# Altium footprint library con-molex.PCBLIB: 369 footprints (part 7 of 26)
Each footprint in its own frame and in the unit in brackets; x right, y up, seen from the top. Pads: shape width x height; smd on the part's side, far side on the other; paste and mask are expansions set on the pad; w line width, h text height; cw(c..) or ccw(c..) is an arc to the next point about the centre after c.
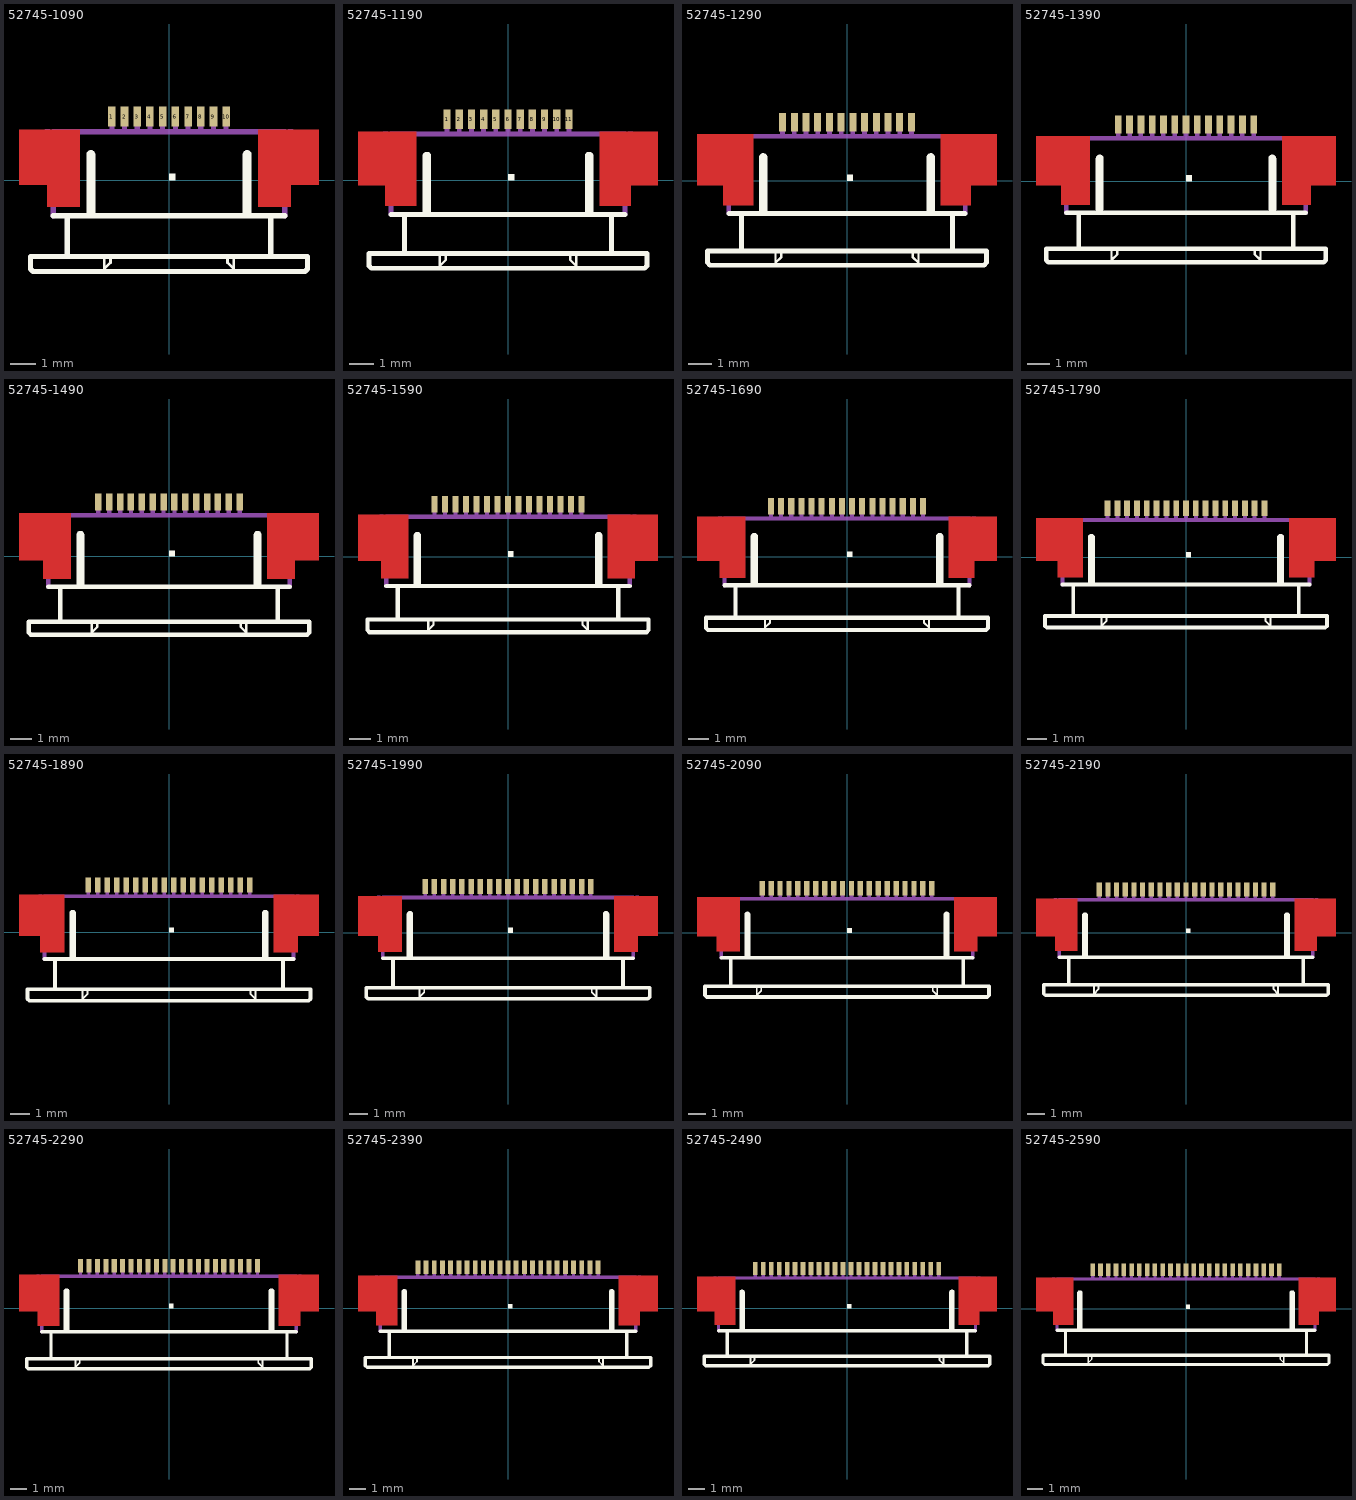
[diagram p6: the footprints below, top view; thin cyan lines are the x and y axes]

## 52745-1090 [mil]
pads (10):
  rect 11.81x31.5 smd: 1(-88.58,98.43) 2(-68.9,98.43) 3(-49.21,98.43) 4(-29.53,98.43) 5(-9.84,98.43) 6(9.84,98.43) 7(29.53,98.43) 8(49.21,98.43) 9(68.9,98.43) 10(88.58,98.43)
Top Layer:
  rectangle: -232.28,-7.87 -137.8,78.74
  rectangle: -188.98,-41.34 -137.8,-7.87
  rectangle: 137.8,-41.34 188.98,-7.87
  rectangle: 137.8,-7.87 232.28,78.74
Top Overlay:
  region: 0,0 10,0 10,10 0,10
  lines w4: -100.39,-122.05 -100.39,-137.8 -90.55,-127.95 -90.55,-122.05 ; 90.55,-122.05 90.55,-127.95 100.39,-137.8 100.39,-122.05
  lines w8: -179.13,-55.12 179.13,-55.12 ; -157.48,-114.17 -157.48,-59.06 ; -124.02,-49.21 -124.02,39.37 cw(c-121.06,39.37) -118.11,39.37 -118.11,-49.21 ; 118.11,-49.21 118.11,39.37 cw(c121.06,39.37) 124.02,39.37 124.02,-49.21 ; 157.48,-114.17 157.48,-59.06 ; -214.57,-137.8 -214.57,-118.11 214.57,-118.11 214.57,-137.8 210.63,-141.73 -210.63,-141.73 -214.57,-137.8
Top Paste:
  region: 224.41,72.83 145.67,72.83 145.67,-1.97 224.41,-1.97
  rectangle: -224.41,-1.97 -145.67,72.83
Top Solder:
  region: 232.28,78.74 187.01,78.74 187.01,-7.87 232.28,-7.87
  region: 188.98,78.74 137.8,78.74 137.8,-41.34 188.98,-41.34
  rectangle: -232.28,-7.87 -187.01,78.74
  rectangle: -188.98,-41.34 -137.8,78.74
Mechanical 16:
  rectangle: -92.52,78.74 -84.65,106.3
  rectangle: -72.83,78.74 -64.96,106.3
  rectangle: -53.15,78.74 -45.28,106.3
  rectangle: -33.46,78.74 -25.59,106.3
  rectangle: -13.78,78.74 -5.91,106.3
  rectangle: 5.91,78.74 13.78,106.3
  rectangle: 25.59,78.74 33.46,106.3
  rectangle: 45.28,78.74 53.15,106.3
  rectangle: 64.96,78.74 72.83,106.3
  rectangle: 84.65,78.74 92.52,106.3
  lines w4: -185.04,74.8 -185.04,27.56 -214.57,27.56 -214.57,35.43 -192.91,35.43 -190.94,37.4 -190.94,57.09 -214.57,57.09 -214.57,64.96 -190.94,64.96 -190.94,76.77 -185.04,76.77 ; 185.04,74.8 185.04,27.56 214.57,27.56 214.57,35.43 192.91,35.43 190.94,37.4 190.94,57.09 214.57,57.09 214.57,64.96 190.94,64.96 190.94,76.77 185.04,76.77
  lines w8: -179.13,-55.12 -179.13,74.8 179.13,74.8 179.13,-55.12

## 52745-1190 [mil]
pads (11):
  rect 11.81x31.5 smd: 1(-98.43,98.43) 2(-78.74,98.43) 3(-59.06,98.43) 4(-39.37,98.43) 5(-19.69,98.43) 6(0,98.43) 7(19.69,98.43) 8(39.37,98.43) 9(59.06,98.43) 10(78.74,98.43) 11(98.43,98.43)
Top Layer:
  rectangle: -242.13,-7.87 -147.64,78.74
  rectangle: -198.82,-41.34 -147.64,-7.87
  rectangle: 147.64,-41.34 198.82,-7.87
  rectangle: 147.64,-7.87 242.13,78.74
Top Overlay:
  region: 0,0 10,0 10,10 0,10
  lines w4: -110.24,-122.05 -110.24,-137.8 -100.39,-127.95 -100.39,-122.05 ; 100.39,-122.05 100.39,-127.95 110.24,-137.8 110.24,-122.05
  lines w8: -188.98,-55.12 188.98,-55.12 ; -167.32,-114.17 -167.32,-59.06 ; -133.86,-49.21 -133.86,39.37 cw(c-130.91,39.37) -127.95,39.37 -127.95,-49.21 ; 127.95,-49.21 127.95,39.37 cw(c130.91,39.37) 133.86,39.37 133.86,-49.21 ; 167.32,-114.17 167.32,-59.06 ; -224.41,-137.8 -224.41,-118.11 224.41,-118.11 224.41,-137.8 220.47,-141.73 -220.47,-141.73 -224.41,-137.8
Top Paste:
  region: 234.25,72.83 155.51,72.83 155.51,-1.97 234.25,-1.97
  rectangle: -234.25,-1.97 -155.51,72.83
Top Solder:
  region: 242.13,78.74 196.85,78.74 196.85,-7.87 242.13,-7.87
  region: 198.82,78.74 147.64,78.74 147.64,-41.34 198.82,-41.34
  rectangle: -242.13,-7.87 -196.85,78.74
  rectangle: -198.82,-41.34 -147.64,78.74
Mechanical 16:
  rectangle: -102.36,78.74 -94.49,106.3
  rectangle: -82.68,78.74 -74.8,106.3
  rectangle: -62.99,78.74 -55.12,106.3
  rectangle: -43.31,78.74 -35.43,106.3
  rectangle: -23.62,78.74 -15.75,106.3
  rectangle: -3.94,78.74 3.94,106.3
  rectangle: 15.75,78.74 23.62,106.3
  rectangle: 35.43,78.74 43.31,106.3
  rectangle: 55.12,78.74 62.99,106.3
  rectangle: 74.8,78.74 82.68,106.3
  rectangle: 94.49,78.74 102.36,106.3
  lines w4: -194.88,74.8 -194.88,27.56 -224.41,27.56 -224.41,35.43 -202.76,35.43 -200.79,37.4 -200.79,57.09 -224.41,57.09 -224.41,64.96 -200.79,64.96 -200.79,76.77 -194.88,76.77 ; 194.88,74.8 194.88,27.56 224.41,27.56 224.41,35.43 202.76,35.43 200.79,37.4 200.79,57.09 224.41,57.09 224.41,64.96 200.79,64.96 200.79,76.77 194.88,76.77
  lines w8: -188.98,-55.12 -188.98,74.8 188.98,74.8 188.98,-55.12

## 52745-1290 [mil]
pads (12):
  rect 11.81x31.5 smd: 1(-108.27,98.43) 2(-88.58,98.43) 3(-68.9,98.43) 4(-49.21,98.43) 5(-29.53,98.43) 6(-9.84,98.43) 7(9.84,98.43) 8(29.53,98.43) 9(49.21,98.43) 10(68.9,98.43) 11(88.58,98.43) 12(108.27,98.43)
Top Layer:
  rectangle: -251.97,-7.87 -157.48,78.74
  rectangle: -208.66,-41.34 -157.48,-7.87
  rectangle: 157.48,-7.87 251.97,78.74
  rectangle: 157.48,-41.34 208.66,-7.87
Top Overlay:
  region: 0,0 10,0 10,10 0,10
  lines w4: -120.08,-122.05 -120.08,-137.8 -110.24,-127.95 -110.24,-122.05 ; 110.24,-122.05 110.24,-127.95 120.08,-137.8 120.08,-122.05
  lines w8: -198.82,-55.12 198.82,-55.12 ; -177.17,-114.17 -177.17,-59.06 ; -143.7,-49.21 -143.7,39.37 cw(c-140.75,39.37) -137.8,39.37 -137.8,-49.21 ; 137.8,-49.21 137.8,39.37 cw(c140.75,39.37) 143.7,39.37 143.7,-49.21 ; 177.17,-114.17 177.17,-59.06 ; -234.25,-137.8 -234.25,-118.11 234.25,-118.11 234.25,-137.8 230.32,-141.73 -230.32,-141.73 -234.25,-137.8
Top Paste:
  region: 244.09,72.83 165.35,72.83 165.35,-1.97 244.09,-1.97
  rectangle: -244.09,-1.97 -165.35,72.83
Top Solder:
  region: 251.97,78.74 206.69,78.74 206.69,-7.87 251.97,-7.87
  region: 208.66,78.74 157.48,78.74 157.48,-41.34 208.66,-41.34
  rectangle: -251.97,-7.87 -206.69,78.74
  rectangle: -208.66,-41.34 -157.48,78.74
Mechanical 16:
  rectangle: -112.2,78.74 -104.33,106.3
  rectangle: -92.52,78.74 -84.65,106.3
  rectangle: -72.83,78.74 -64.96,106.3
  rectangle: -53.15,78.74 -45.28,106.3
  rectangle: -33.46,78.74 -25.59,106.3
  rectangle: -13.78,78.74 -5.91,106.3
  rectangle: 5.91,78.74 13.78,106.3
  rectangle: 25.59,78.74 33.46,106.3
  rectangle: 45.28,78.74 53.15,106.3
  rectangle: 64.96,78.74 72.83,106.3
  rectangle: 84.65,78.74 92.52,106.3
  rectangle: 104.33,78.74 112.2,106.3
  lines w4: -204.72,74.8 -204.72,27.56 -234.25,27.56 -234.25,35.43 -212.6,35.43 -210.63,37.4 -210.63,57.09 -234.25,57.09 -234.25,64.96 -210.63,64.96 -210.63,76.77 -204.72,76.77 ; 204.72,74.8 204.72,27.56 234.25,27.56 234.25,35.43 212.6,35.43 210.63,37.4 210.63,57.09 234.25,57.09 234.25,64.96 210.63,64.96 210.63,76.77 204.72,76.77
  lines w8: -198.82,-55.12 -198.82,74.8 198.82,74.8 198.82,-55.12

## 52745-1390 [mil]
pads (13):
  rect 11.81x31.5 smd: 1(-118.11,98.43) 2(-98.43,98.43) 3(-78.74,98.43) 4(-59.06,98.43) 5(-39.37,98.43) 6(-19.69,98.43) 7(0,98.43) 8(19.69,98.43) 9(39.37,98.43) 10(59.06,98.43) 11(78.74,98.43) 12(98.43,98.43) 13(118.11,98.43)
Top Layer:
  rectangle: -261.81,-7.87 -167.32,78.74
  rectangle: -218.5,-41.34 -167.32,-7.87
  rectangle: 167.32,-7.87 261.81,78.74
  rectangle: 167.32,-41.34 218.5,-7.87
Top Overlay:
  region: 0,0 10,0 10,10 0,10
  lines w4: -129.92,-122.05 -129.92,-137.8 -120.08,-127.95 -120.08,-122.05 ; 120.08,-122.05 120.08,-127.95 129.92,-137.8 129.92,-122.05
  lines w8: -208.66,-55.12 208.66,-55.12 ; -187.01,-114.17 -187.01,-59.06 ; -153.54,-49.21 -153.54,39.37 cw(c-150.59,39.37) -147.64,39.37 -147.64,-49.21 ; 147.64,-49.21 147.64,39.37 cw(c150.59,39.37) 153.54,39.37 153.54,-49.21 ; 187.01,-114.17 187.01,-59.06 ; -244.09,-137.8 -244.09,-118.11 244.09,-118.11 244.09,-137.8 240.16,-141.73 -240.16,-141.73 -244.09,-137.8
Top Paste:
  region: 253.94,72.83 175.2,72.83 175.2,-1.97 253.94,-1.97
  rectangle: -253.94,-1.97 -175.2,72.83
Top Solder:
  region: 261.81,78.74 216.54,78.74 216.54,-7.87 261.81,-7.87
  region: 218.5,78.74 167.32,78.74 167.32,-41.34 218.5,-41.34
  rectangle: -261.81,-7.87 -216.54,78.74
  rectangle: -218.5,-41.34 -167.32,78.74
Mechanical 16:
  rectangle: -122.05,78.74 -114.17,106.3
  rectangle: -102.36,78.74 -94.49,106.3
  rectangle: -82.68,78.74 -74.8,106.3
  rectangle: -62.99,78.74 -55.12,106.3
  rectangle: -43.31,78.74 -35.43,106.3
  rectangle: -23.62,78.74 -15.75,106.3
  rectangle: -3.94,78.74 3.94,106.3
  rectangle: 15.75,78.74 23.62,106.3
  rectangle: 35.43,78.74 43.31,106.3
  rectangle: 55.12,78.74 62.99,106.3
  rectangle: 74.8,78.74 82.68,106.3
  rectangle: 94.49,78.74 102.36,106.3
  rectangle: 114.17,78.74 122.05,106.3
  lines w4: -214.57,74.8 -214.57,27.56 -244.09,27.56 -244.09,35.43 -222.44,35.43 -220.47,37.4 -220.47,57.09 -244.09,57.09 -244.09,64.96 -220.47,64.96 -220.47,76.77 -214.57,76.77 ; 214.57,74.8 214.57,27.56 244.09,27.56 244.09,35.43 222.44,35.43 220.47,37.4 220.47,57.09 244.09,57.09 244.09,64.96 220.47,64.96 220.47,76.77 214.57,76.77
  lines w8: -208.66,-55.12 -208.66,74.8 208.66,74.8 208.66,-55.12

## 52745-1490 [mil]
pads (14):
  rect 11.81x31.5 smd: 1(-127.95,98.43) 2(-108.27,98.43) 3(-88.58,98.43) 4(-68.9,98.43) 5(-49.21,98.43) 6(-29.53,98.43) 7(-9.84,98.43) 8(9.84,98.43) 9(29.53,98.43) 10(49.21,98.43) 11(68.9,98.43) 12(88.58,98.43) 13(108.27,98.43) 14(127.95,98.43)
Top Layer:
  rectangle: -271.65,-7.87 -177.17,78.74
  rectangle: -228.35,-41.34 -177.17,-7.87
  rectangle: 177.17,-7.87 271.65,78.74
  rectangle: 177.17,-41.34 228.35,-7.87
Top Overlay:
  region: 0,0 10,0 10,10 0,10
  lines w4: -139.76,-122.05 -139.76,-137.8 -129.92,-127.95 -129.92,-122.05 ; 129.92,-122.05 129.92,-127.95 139.76,-137.8 139.76,-122.05
  lines w8: -218.5,-55.12 218.5,-55.12 ; -196.85,-114.17 -196.85,-59.06 ; -163.39,-49.21 -163.39,39.37 cw(c-160.44,39.37) -157.48,39.37 -157.48,-49.21 ; 157.48,-49.21 157.48,39.37 cw(c160.44,39.37) 163.39,39.37 163.39,-49.21 ; 196.85,-114.17 196.85,-59.06 ; -253.94,-137.8 -253.94,-118.11 253.94,-118.11 253.94,-137.8 250,-141.73 -250,-141.73 -253.94,-137.8
Top Paste:
  region: 263.78,72.83 185.04,72.83 185.04,-1.97 263.78,-1.97
  rectangle: -263.78,-1.97 -185.04,72.83
Top Solder:
  region: 271.65,78.74 226.38,78.74 226.38,-7.87 271.65,-7.87
  region: 228.35,78.74 177.17,78.74 177.17,-41.34 228.35,-41.34
  rectangle: -271.65,-7.87 -226.38,78.74
  rectangle: -228.35,-41.34 -177.17,78.74
Mechanical 16:
  rectangle: -131.89,78.74 -124.02,106.3
  rectangle: -112.2,78.74 -104.33,106.3
  rectangle: -92.52,78.74 -84.65,106.3
  rectangle: -72.83,78.74 -64.96,106.3
  rectangle: -53.15,78.74 -45.28,106.3
  rectangle: -33.46,78.74 -25.59,106.3
  rectangle: -13.78,78.74 -5.91,106.3
  rectangle: 5.91,78.74 13.78,106.3
  rectangle: 25.59,78.74 33.46,106.3
  rectangle: 45.28,78.74 53.15,106.3
  rectangle: 64.96,78.74 72.83,106.3
  rectangle: 84.65,78.74 92.52,106.3
  rectangle: 104.33,78.74 112.2,106.3
  rectangle: 124.02,78.74 131.89,106.3
  lines w4: -224.41,74.8 -224.41,27.56 -253.94,27.56 -253.94,35.43 -232.28,35.43 -230.32,37.4 -230.32,57.09 -253.94,57.09 -253.94,64.96 -230.32,64.96 -230.32,76.77 -224.41,76.77 ; 224.41,74.8 224.41,27.56 253.94,27.56 253.94,35.43 232.28,35.43 230.32,37.4 230.32,57.09 253.94,57.09 253.94,64.96 230.32,64.96 230.32,76.77 224.41,76.77
  lines w8: -218.5,-55.12 -218.5,74.8 218.5,74.8 218.5,-55.12

## 52745-1590 [mil]
pads (15):
  rect 11.81x31.5 smd: 1(-137.8,98.43) 2(-118.11,98.43) 3(-98.43,98.43) 4(-78.74,98.43) 5(-59.06,98.43) 6(-39.37,98.43) 7(-19.69,98.43) 8(0,98.43) 9(19.69,98.43) 10(39.37,98.43) 11(59.06,98.43) 12(78.74,98.43) 13(98.43,98.43) 14(118.11,98.43) 15(137.8,98.43)
Top Layer:
  rectangle: -281.5,-7.87 -187.01,78.74
  rectangle: -238.19,-41.34 -187.01,-7.87
  rectangle: 187.01,-7.87 281.5,78.74
  rectangle: 187.01,-41.34 238.19,-7.87
Top Overlay:
  region: 0,0 10,0 10,10 0,10
  lines w4: -149.61,-122.05 -149.61,-137.8 -139.76,-127.95 -139.76,-122.05 ; 139.76,-122.05 139.76,-127.95 149.61,-137.8 149.61,-122.05
  lines w8: -228.35,-55.12 228.35,-55.12 ; -206.69,-114.17 -206.69,-59.06 ; -173.23,-49.21 -173.23,39.37 cw(c-170.28,39.37) -167.32,39.37 -167.32,-49.21 ; 167.32,-49.21 167.32,39.37 cw(c170.28,39.37) 173.23,39.37 173.23,-49.21 ; 206.69,-114.17 206.69,-59.06 ; -263.78,-137.8 -263.78,-118.11 263.78,-118.11 263.78,-137.8 259.84,-141.73 -259.84,-141.73 -263.78,-137.8
Top Paste:
  region: 273.62,72.83 194.88,72.83 194.88,-1.97 273.62,-1.97
  rectangle: -273.62,-1.97 -194.88,72.83
Top Solder:
  region: 281.5,78.74 236.22,78.74 236.22,-7.87 281.5,-7.87
  region: 238.19,78.74 187.01,78.74 187.01,-41.34 238.19,-41.34
  rectangle: -281.5,-7.87 -236.22,78.74
  rectangle: -238.19,-41.34 -187.01,78.74
Mechanical 16:
  rectangle: -141.73,78.74 -133.86,106.3
  rectangle: -122.05,78.74 -114.17,106.3
  rectangle: -102.36,78.74 -94.49,106.3
  rectangle: -82.68,78.74 -74.8,106.3
  rectangle: -62.99,78.74 -55.12,106.3
  rectangle: -43.31,78.74 -35.43,106.3
  rectangle: -23.62,78.74 -15.75,106.3
  rectangle: -3.94,78.74 3.94,106.3
  rectangle: 15.75,78.74 23.62,106.3
  rectangle: 35.43,78.74 43.31,106.3
  rectangle: 55.12,78.74 62.99,106.3
  rectangle: 74.8,78.74 82.68,106.3
  rectangle: 94.49,78.74 102.36,106.3
  rectangle: 114.17,78.74 122.05,106.3
  rectangle: 133.86,78.74 141.73,106.3
  lines w4: -234.25,74.8 -234.25,27.56 -263.78,27.56 -263.78,35.43 -242.13,35.43 -240.16,37.4 -240.16,57.09 -263.78,57.09 -263.78,64.96 -240.16,64.96 -240.16,76.77 -234.25,76.77 ; 234.25,74.8 234.25,27.56 263.78,27.56 263.78,35.43 242.13,35.43 240.16,37.4 240.16,57.09 263.78,57.09 263.78,64.96 240.16,64.96 240.16,76.77 234.25,76.77
  lines w8: -228.35,-55.12 -228.35,74.8 228.35,74.8 228.35,-55.12

## 52745-1690 [mil]
pads (16):
  rect 11.81x31.5 smd: 1(-147.64,98.43) 2(-127.95,98.43) 3(-108.27,98.43) 4(-88.58,98.43) 5(-68.9,98.43) 6(-49.21,98.43) 7(-29.53,98.43) 8(-9.84,98.43) 9(9.84,98.43) 10(29.53,98.43) 11(49.21,98.43) 12(68.9,98.43) 13(88.58,98.43) 14(108.27,98.43) 15(127.95,98.43) 16(147.64,98.43)
Top Layer:
  rectangle: -291.34,-7.87 -196.85,78.74
  rectangle: -248.03,-41.34 -196.85,-7.87
  rectangle: 196.85,-7.87 291.34,78.74
  rectangle: 196.85,-41.34 248.03,-7.87
Top Overlay:
  region: 0,0 10,0 10,10 0,10
  lines w4: -159.45,-122.05 -159.45,-137.8 -149.61,-127.95 -149.61,-122.05 ; 149.61,-122.05 149.61,-127.95 159.45,-137.8 159.45,-122.05
  lines w8: -238.19,-55.12 238.19,-55.12 ; -216.54,-114.17 -216.54,-59.06 ; -183.07,-49.21 -183.07,39.37 cw(c-180.12,39.37) -177.17,39.37 -177.17,-49.21 ; 177.17,-49.21 177.17,39.37 cw(c180.12,39.37) 183.07,39.37 183.07,-49.21 ; 216.54,-114.17 216.54,-59.06 ; -273.62,-137.8 -273.62,-118.11 273.62,-118.11 273.62,-137.8 269.69,-141.73 -269.69,-141.73 -273.62,-137.8
Top Paste:
  region: 283.46,72.83 204.72,72.83 204.72,-1.97 283.46,-1.97
  rectangle: -283.46,-1.97 -204.72,72.83
Top Solder:
  region: 291.34,78.74 246.06,78.74 246.06,-7.87 291.34,-7.87
  region: 248.03,78.74 196.85,78.74 196.85,-41.34 248.03,-41.34
  rectangle: -291.34,-7.87 -246.06,78.74
  rectangle: -248.03,-41.34 -196.85,78.74
Mechanical 16:
  rectangle: -151.57,78.74 -143.7,106.3
  rectangle: -131.89,78.74 -124.02,106.3
  rectangle: -112.2,78.74 -104.33,106.3
  rectangle: -92.52,78.74 -84.65,106.3
  rectangle: -72.83,78.74 -64.96,106.3
  rectangle: -53.15,78.74 -45.28,106.3
  rectangle: -33.46,78.74 -25.59,106.3
  rectangle: -13.78,78.74 -5.91,106.3
  rectangle: 5.91,78.74 13.78,106.3
  rectangle: 25.59,78.74 33.46,106.3
  rectangle: 45.28,78.74 53.15,106.3
  rectangle: 64.96,78.74 72.83,106.3
  rectangle: 84.65,78.74 92.52,106.3
  rectangle: 104.33,78.74 112.2,106.3
  rectangle: 124.02,78.74 131.89,106.3
  rectangle: 143.7,78.74 151.57,106.3
  lines w4: -244.09,74.8 -244.09,27.56 -273.62,27.56 -273.62,35.43 -251.97,35.43 -250,37.4 -250,57.09 -273.62,57.09 -273.62,64.96 -250,64.96 -250,76.77 -244.09,76.77 ; 244.09,74.8 244.09,27.56 273.62,27.56 273.62,35.43 251.97,35.43 250,37.4 250,57.09 273.62,57.09 273.62,64.96 250,64.96 250,76.77 244.09,76.77
  lines w8: -238.19,-55.12 -238.19,74.8 238.19,74.8 238.19,-55.12

## 52745-1790 [mil]
pads (17):
  rect 11.81x31.5 smd: 1(-157.48,98.43) 2(-137.8,98.43) 3(-118.11,98.43) 4(-98.43,98.43) 5(-78.74,98.43) 6(-59.06,98.43) 7(-39.37,98.43) 8(-19.69,98.43) 9(0,98.43) 10(19.69,98.43) 11(39.37,98.43) 12(59.06,98.43) 13(78.74,98.43) 14(98.43,98.43) 15(118.11,98.43) 16(137.8,98.43) 17(157.48,98.43)
Top Layer:
  rectangle: -301.18,-7.87 -206.69,78.74
  rectangle: -257.87,-41.34 -206.69,-6.89
  rectangle: 206.69,-41.34 257.87,-6.89
  rectangle: 206.69,-7.87 301.18,78.74
Top Overlay:
  region: 0,0 10,0 10,10 0,10
  lines w4: -169.29,-122.05 -169.29,-137.8 -159.45,-127.95 -159.45,-122.05 ; 159.45,-122.05 159.45,-127.95 169.29,-137.8 169.29,-122.05
  lines w8: -248.03,-55.12 248.03,-55.12 ; -226.38,-114.17 -226.38,-59.06 ; -192.91,-49.21 -192.91,39.37 cw(c-189.96,39.37) -187.01,39.37 -187.01,-49.21 ; 187.01,-49.21 187.01,39.37 cw(c189.96,39.37) 192.91,39.37 192.91,-49.21 ; 226.38,-114.17 226.38,-59.06 ; -283.46,-137.8 -283.46,-118.11 283.46,-118.11 283.46,-137.8 279.53,-141.73 -279.53,-141.73 -283.46,-137.8
Top Paste:
  region: 293.31,72.83 214.57,72.83 214.57,-1.97 293.31,-1.97
  rectangle: -293.31,-1.97 -214.57,72.83
Top Solder:
  region: 301.18,78.74 255.91,78.74 255.91,-7.87 301.18,-7.87
  region: 257.87,78.74 206.69,78.74 206.69,-41.34 257.87,-41.34
  rectangle: -301.18,-7.87 -255.91,78.74
  rectangle: -257.87,-41.34 -206.69,78.74
Mechanical 16:
  rectangle: -161.42,78.74 -153.54,106.3
  rectangle: -141.73,78.74 -133.86,106.3
  rectangle: -122.05,78.74 -114.17,106.3
  rectangle: -102.36,78.74 -94.49,106.3
  rectangle: -82.68,78.74 -74.8,106.3
  rectangle: -62.99,78.74 -55.12,106.3
  rectangle: -43.31,78.74 -35.43,106.3
  rectangle: -23.62,78.74 -15.75,106.3
  rectangle: -3.94,78.74 3.94,106.3
  rectangle: 15.75,78.74 23.62,106.3
  rectangle: 35.43,78.74 43.31,106.3
  rectangle: 55.12,78.74 62.99,106.3
  rectangle: 74.8,78.74 82.68,106.3
  rectangle: 94.49,78.74 102.36,106.3
  rectangle: 114.17,78.74 122.05,106.3
  rectangle: 133.86,78.74 141.73,106.3
  rectangle: 153.54,78.74 161.42,106.3
  lines w4: -253.94,74.8 -253.94,27.56 -283.46,27.56 -283.46,35.43 -261.81,35.43 -259.84,37.4 -259.84,57.09 -283.46,57.09 -283.46,64.96 -259.84,64.96 -259.84,76.77 -253.94,76.77 ; 253.94,74.8 253.94,27.56 283.46,27.56 283.46,35.43 261.81,35.43 259.84,37.4 259.84,57.09 283.46,57.09 283.46,64.96 259.84,64.96 259.84,76.77 253.94,76.77
  lines w8: -248.03,-55.12 -248.03,74.8 248.03,74.8 248.03,-55.12

## 52745-1890 [mil]
pads (18):
  rect 11.81x31.5 smd: 1(-167.32,98.43) 2(-147.64,98.43) 3(-127.95,98.43) 4(-108.27,98.43) 5(-88.58,98.43) 6(-68.9,98.43) 7(-49.21,98.43) 8(-29.53,98.43) 9(-9.84,98.43) 10(9.84,98.43) 11(29.53,98.43) 12(49.21,98.43) 13(68.9,98.43) 14(88.58,98.43) 15(108.27,98.43) 16(127.95,98.43) 17(147.64,98.43) 18(167.32,98.43)
Top Layer:
  rectangle: -311.02,-7.87 -216.54,78.74
  rectangle: -267.72,-41.34 -216.54,-7.87
  rectangle: 216.54,-41.34 267.72,-7.87
  rectangle: 216.54,-7.87 311.02,78.74
Top Overlay:
  region: 0,0 10,0 10,10 0,10
  lines w4: -179.13,-122.05 -179.13,-137.8 -169.29,-127.95 -169.29,-122.05 ; 169.29,-122.05 169.29,-127.95 179.13,-137.8 179.13,-122.05
  lines w8: -257.87,-55.12 257.87,-55.12 ; -236.22,-114.17 -236.22,-59.06 ; -202.76,-49.21 -202.76,39.37 cw(c-199.81,39.37) -196.85,39.37 -196.85,-49.21 ; 196.85,-49.21 196.85,39.37 cw(c199.81,39.37) 202.76,39.37 202.76,-49.21 ; 236.22,-114.17 236.22,-59.06 ; -293.31,-137.8 -293.31,-118.11 293.31,-118.11 293.31,-137.8 289.37,-141.73 -289.37,-141.73 -293.31,-137.8
Top Paste:
  region: 303.15,72.83 224.41,72.83 224.41,-1.97 303.15,-1.97
  rectangle: -303.15,-1.97 -224.41,72.83
Top Solder:
  region: 311.02,78.74 265.75,78.74 265.75,-7.87 311.02,-7.87
  region: 267.72,78.74 216.54,78.74 216.54,-41.34 267.72,-41.34
  rectangle: -311.02,-7.87 -265.75,78.74
  rectangle: -267.72,-41.34 -216.54,78.74
Mechanical 16:
  rectangle: -171.26,78.74 -163.39,106.3
  rectangle: -151.57,78.74 -143.7,106.3
  rectangle: -131.89,78.74 -124.02,106.3
  rectangle: -112.2,78.74 -104.33,106.3
  rectangle: -92.52,78.74 -84.65,106.3
  rectangle: -72.83,78.74 -64.96,106.3
  rectangle: -53.15,78.74 -45.28,106.3
  rectangle: -33.46,78.74 -25.59,106.3
  rectangle: -13.78,78.74 -5.91,106.3
  rectangle: 5.91,78.74 13.78,106.3
  rectangle: 25.59,78.74 33.46,106.3
  rectangle: 45.28,78.74 53.15,106.3
  rectangle: 64.96,78.74 72.83,106.3
  rectangle: 84.65,78.74 92.52,106.3
  rectangle: 104.33,78.74 112.2,106.3
  rectangle: 124.02,78.74 131.89,106.3
  rectangle: 143.7,78.74 151.57,106.3
  rectangle: 163.39,78.74 171.26,106.3
  lines w4: -263.78,74.8 -263.78,27.56 -293.31,27.56 -293.31,35.43 -271.65,35.43 -269.69,37.4 -269.69,57.09 -293.31,57.09 -293.31,64.96 -269.69,64.96 -269.69,76.77 -263.78,76.77 ; 263.78,74.8 263.78,27.56 293.31,27.56 293.31,35.43 271.65,35.43 269.69,37.4 269.69,57.09 293.31,57.09 293.31,64.96 269.69,64.96 269.69,76.77 263.78,76.77
  lines w8: -257.87,-55.12 -257.87,74.8 257.87,74.8 257.87,-55.12

## 52745-1990 [mil]
pads (19):
  rect 11.81x31.5 smd: 1(-177.17,98.43) 2(-157.48,98.43) 3(-137.8,98.43) 4(-118.11,98.43) 5(-98.43,98.43) 6(-78.74,98.43) 7(-59.06,98.43) 8(-39.37,98.43) 9(-19.69,98.43) 10(0,98.43) 11(19.69,98.43) 12(39.37,98.43) 13(59.06,98.43) 14(78.74,98.43) 15(98.43,98.43) 16(118.11,98.43) 17(137.8,98.43) 18(157.48,98.43) 19(177.17,98.43)
Top Layer:
  rectangle: -320.87,-7.87 -226.38,78.74
  rectangle: -277.56,-41.34 -226.38,-7.87
  rectangle: 226.38,-41.34 277.56,-7.87
  rectangle: 226.38,-7.87 320.87,78.74
Top Overlay:
  region: 0,0 10,0 10,10 0,10
  lines w4: -188.98,-122.05 -188.98,-137.8 -179.13,-127.95 -179.13,-122.05 ; 179.13,-122.05 179.13,-127.95 188.98,-137.8 188.98,-122.05
  lines w8: -267.72,-55.12 267.72,-55.12 ; -246.06,-114.17 -246.06,-59.06 ; -212.6,-49.21 -212.6,39.37 cw(c-209.65,39.37) -206.69,39.37 -206.69,-49.21 ; 206.69,-49.21 206.69,39.37 cw(c209.65,39.37) 212.6,39.37 212.6,-49.21 ; 246.06,-114.17 246.06,-59.06 ; -303.15,-137.8 -303.15,-118.11 303.15,-118.11 303.15,-137.8 299.21,-141.73 -299.21,-141.73 -303.15,-137.8
Top Paste:
  region: 312.99,72.83 234.25,72.83 234.25,-1.97 312.99,-1.97
  rectangle: -312.99,-1.97 -234.25,72.83
Top Solder:
  region: 320.87,78.74 275.59,78.74 275.59,-7.87 320.87,-7.87
  region: 277.56,78.74 226.38,78.74 226.38,-41.34 277.56,-41.34
  rectangle: -320.87,-7.87 -275.59,78.74
  rectangle: -277.56,-41.34 -226.38,78.74
Mechanical 16:
  rectangle: -181.1,78.74 -173.23,106.3
  rectangle: -161.42,78.74 -153.54,106.3
  rectangle: -141.73,78.74 -133.86,106.3
  rectangle: -122.05,78.74 -114.17,106.3
  rectangle: -102.36,78.74 -94.49,106.3
  rectangle: -82.68,78.74 -74.8,106.3
  rectangle: -62.99,78.74 -55.12,106.3
  rectangle: -43.31,78.74 -35.43,106.3
  rectangle: -23.62,78.74 -15.75,106.3
  rectangle: -3.94,78.74 3.94,106.3
  rectangle: 15.75,78.74 23.62,106.3
  rectangle: 35.43,78.74 43.31,106.3
  rectangle: 55.12,78.74 62.99,106.3
  rectangle: 74.8,78.74 82.68,106.3
  rectangle: 94.49,78.74 102.36,106.3
  rectangle: 114.17,78.74 122.05,106.3
  rectangle: 133.86,78.74 141.73,106.3
  rectangle: 153.54,78.74 161.42,106.3
  rectangle: 173.23,78.74 181.1,106.3
  lines w4: -273.62,74.8 -273.62,27.56 -303.15,27.56 -303.15,35.43 -281.5,35.43 -279.53,37.4 -279.53,57.09 -303.15,57.09 -303.15,64.96 -279.53,64.96 -279.53,76.77 -273.62,76.77 ; 273.62,74.8 273.62,27.56 303.15,27.56 303.15,35.43 281.5,35.43 279.53,37.4 279.53,57.09 303.15,57.09 303.15,64.96 279.53,64.96 279.53,76.77 273.62,76.77
  lines w8: -267.72,-55.12 -267.72,74.8 267.72,74.8 267.72,-55.12

## 52745-2090 [mil]
pads (20):
  rect 11.81x31.5 smd: 1(-187.01,98.43) 2(-167.32,98.43) 3(-147.64,98.43) 4(-127.95,98.43) 5(-108.27,98.43) 6(-88.58,98.43) 7(-68.9,98.43) 8(-49.21,98.43) 9(-29.53,98.43) 10(-9.84,98.43) 11(9.84,98.43) 12(29.53,98.43) 13(49.21,98.43) 14(68.9,98.43) 15(88.58,98.43) 16(108.27,98.43) 17(127.95,98.43) 18(147.64,98.43) 19(167.32,98.43) 20(187.01,98.43)
Top Layer:
  rectangle: -330.71,-7.87 -236.22,78.74
  rectangle: -287.4,-41.34 -236.22,-7.87
  rectangle: 236.22,-41.34 287.4,-7.87
  rectangle: 236.22,-7.87 330.71,78.74
Top Overlay:
  region: 0,0 10,0 10,10 0,10
  lines w4: -198.82,-122.05 -198.82,-137.8 -188.98,-127.95 -188.98,-122.05 ; 188.98,-122.05 188.98,-127.95 198.82,-137.8 198.82,-122.05
  lines w8: -277.56,-55.12 277.56,-55.12 ; -255.91,-114.17 -255.91,-59.06 ; -222.44,-49.21 -222.44,39.37 cw(c-219.49,39.37) -216.54,39.37 -216.54,-49.21 ; 216.54,-49.21 216.54,39.37 cw(c219.49,39.37) 222.44,39.37 222.44,-49.21 ; 255.91,-114.17 255.91,-59.06 ; -312.99,-137.8 -312.99,-118.11 312.99,-118.11 312.99,-137.8 309.06,-141.73 -309.06,-141.73 -312.99,-137.8
Top Paste:
  region: 322.83,72.83 244.09,72.83 244.09,-1.97 322.83,-1.97
  rectangle: -322.83,-1.97 -244.09,72.83
Top Solder:
  region: 330.71,78.74 285.43,78.74 285.43,-7.87 330.71,-7.87
  region: 287.4,78.74 236.22,78.74 236.22,-41.34 287.4,-41.34
  rectangle: -330.71,-7.87 -285.43,78.74
  rectangle: -287.4,-41.34 -236.22,78.74
Mechanical 16:
  rectangle: -190.94,78.74 -183.07,106.3
  rectangle: -171.26,78.74 -163.39,106.3
  rectangle: -151.57,78.74 -143.7,106.3
  rectangle: -131.89,78.74 -124.02,106.3
  rectangle: -112.2,78.74 -104.33,106.3
  rectangle: -92.52,78.74 -84.65,106.3
  rectangle: -72.83,78.74 -64.96,106.3
  rectangle: -53.15,78.74 -45.28,106.3
  rectangle: -33.46,78.74 -25.59,106.3
  rectangle: -13.78,78.74 -5.91,106.3
  rectangle: 5.91,78.74 13.78,106.3
  rectangle: 25.59,78.74 33.46,106.3
  rectangle: 45.28,78.74 53.15,106.3
  rectangle: 64.96,78.74 72.83,106.3
  rectangle: 84.65,78.74 92.52,106.3
  rectangle: 104.33,78.74 112.2,106.3
  rectangle: 124.02,78.74 131.89,106.3
  rectangle: 143.7,78.74 151.57,106.3
  rectangle: 163.39,78.74 171.26,106.3
  rectangle: 183.07,78.74 190.94,106.3
  lines w4: -283.46,74.8 -283.46,27.56 -312.99,27.56 -312.99,35.43 -291.34,35.43 -289.37,37.4 -289.37,57.09 -312.99,57.09 -312.99,64.96 -289.37,64.96 -289.37,76.77 -283.46,76.77 ; 283.46,74.8 283.46,27.56 312.99,27.56 312.99,35.43 291.34,35.43 289.37,37.4 289.37,57.09 312.99,57.09 312.99,64.96 289.37,64.96 289.37,76.77 283.46,76.77
  lines w8: -277.56,-55.12 -277.56,74.8 277.56,74.8 277.56,-55.12

## 52745-2190 [mil]
pads (21):
  rect 11.81x31.5 smd: 1(-196.85,98.43) 2(-177.17,98.43) 3(-157.48,98.43) 4(-137.8,98.43) 5(-118.11,98.43) 6(-98.43,98.43) 7(-78.74,98.43) 8(-59.06,98.43) 9(-39.37,98.43) 10(-19.69,98.43) 11(0,98.43) 12(19.69,98.43) 13(39.37,98.43) 14(59.06,98.43) 15(78.74,98.43) 16(98.43,98.43) 17(118.11,98.43) 18(137.8,98.43) 19(157.48,98.43) 20(177.17,98.43) 21(196.85,98.43)
Top Layer:
  rectangle: -340.55,-7.87 -246.06,78.74
  rectangle: -297.24,-41.34 -246.06,-7.87
  rectangle: 246.06,-41.34 297.24,-7.87
  rectangle: 246.06,-7.87 340.55,78.74
Top Overlay:
  region: 0,0 10,0 10,10 0,10
  lines w4: -208.66,-122.05 -208.66,-137.8 -198.82,-127.95 -198.82,-122.05 ; 198.82,-122.05 198.82,-127.95 208.66,-137.8 208.66,-122.05
  lines w8: -287.4,-55.12 287.4,-55.12 ; -265.75,-114.17 -265.75,-59.06 ; -232.28,-49.21 -232.28,39.37 cw(c-229.33,39.37) -226.38,39.37 -226.38,-49.21 ; 226.38,-49.21 226.38,39.37 cw(c229.33,39.37) 232.28,39.37 232.28,-49.21 ; 265.75,-114.17 265.75,-59.06 ; -322.83,-137.8 -322.83,-118.11 322.83,-118.11 322.83,-137.8 318.9,-141.73 -318.9,-141.73 -322.83,-137.8
Top Paste:
  region: 332.68,72.83 253.94,72.83 253.94,-1.97 332.68,-1.97
  rectangle: -332.68,-1.97 -253.94,72.83
Top Solder:
  region: 340.55,78.74 295.28,78.74 295.28,-7.87 340.55,-7.87
  region: 297.24,78.74 246.06,78.74 246.06,-41.34 297.24,-41.34
  rectangle: -340.55,-7.87 -295.28,78.74
  rectangle: -297.24,-41.34 -246.06,78.74
Mechanical 16:
  rectangle: -200.79,78.74 -192.91,106.3
  rectangle: -181.1,78.74 -173.23,106.3
  rectangle: -161.42,78.74 -153.54,106.3
  rectangle: -141.73,78.74 -133.86,106.3
  rectangle: -122.05,78.74 -114.17,106.3
  rectangle: -102.36,78.74 -94.49,106.3
  rectangle: -82.68,78.74 -74.8,106.3
  rectangle: -62.99,78.74 -55.12,106.3
  rectangle: -43.31,78.74 -35.43,106.3
  rectangle: -23.62,78.74 -15.75,106.3
  rectangle: -3.94,78.74 3.94,106.3
  rectangle: 15.75,78.74 23.62,106.3
  rectangle: 35.43,78.74 43.31,106.3
  rectangle: 55.12,78.74 62.99,106.3
  rectangle: 74.8,78.74 82.68,106.3
  rectangle: 94.49,78.74 102.36,106.3
  rectangle: 114.17,78.74 122.05,106.3
  rectangle: 133.86,78.74 141.73,106.3
  rectangle: 153.54,78.74 161.42,106.3
  rectangle: 173.23,78.74 181.1,106.3
  rectangle: 192.91,78.74 200.79,106.3
  lines w4: -293.31,74.8 -293.31,27.56 -322.83,27.56 -322.83,35.43 -301.18,35.43 -299.21,37.4 -299.21,57.09 -322.83,57.09 -322.83,64.96 -299.21,64.96 -299.21,76.77 -293.31,76.77 ; 293.31,74.8 293.31,27.56 322.83,27.56 322.83,35.43 301.18,35.43 299.21,37.4 299.21,57.09 322.83,57.09 322.83,64.96 299.21,64.96 299.21,76.77 293.31,76.77
  lines w8: -287.4,-55.12 -287.4,74.8 287.4,74.8 287.4,-55.12

## 52745-2290 [mil]
pads (22):
  rect 11.81x31.5 smd: 1(-206.69,98.43) 2(-187.01,98.43) 3(-167.32,98.43) 4(-147.64,98.43) 5(-127.95,98.43) 6(-108.27,98.43) 7(-88.58,98.43) 8(-68.9,98.43) 9(-49.21,98.43) 10(-29.53,98.43) 11(-9.84,98.43) 12(9.84,98.43) 13(29.53,98.43) 14(49.21,98.43) 15(68.9,98.43) 16(88.58,98.43) 17(108.27,98.43) 18(127.95,98.43) 19(147.64,98.43) 20(167.32,98.43) 21(187.01,98.43) 22(206.69,98.43)
Top Layer:
  rectangle: -350.39,-7.87 -255.91,78.74
  rectangle: -307.09,-41.34 -255.91,-7.87
  rectangle: 255.91,-41.34 307.09,-7.87
  rectangle: 255.91,-7.87 350.39,78.74
Top Overlay:
  region: 0,0 10,0 10,10 0,10
  lines w4: -218.5,-122.05 -218.5,-137.8 -208.66,-127.95 -208.66,-122.05 ; 208.66,-122.05 208.66,-127.95 218.5,-137.8 218.5,-122.05
  lines w8: -297.24,-55.12 297.24,-55.12 ; -275.59,-114.17 -275.59,-59.06 ; -242.13,-49.21 -242.13,39.37 cw(c-239.18,39.37) -236.22,39.37 -236.22,-49.21 ; 236.22,-49.21 236.22,39.37 cw(c239.18,39.37) 242.13,39.37 242.13,-49.21 ; 275.59,-114.17 275.59,-59.06 ; -332.68,-137.8 -332.68,-118.11 332.68,-118.11 332.68,-137.8 328.74,-141.73 -328.74,-141.73 -332.68,-137.8
Top Paste:
  region: 342.52,72.83 263.78,72.83 263.78,-1.97 342.52,-1.97
  rectangle: -342.52,-1.97 -263.78,72.83
Top Solder:
  region: 350.39,78.74 305.12,78.74 305.12,-7.87 350.39,-7.87
  region: 307.09,78.74 255.91,78.74 255.91,-41.34 307.09,-41.34
  rectangle: -350.39,-7.87 -305.12,78.74
  rectangle: -307.09,-41.34 -255.91,78.74
Mechanical 16:
  rectangle: -210.63,78.74 -202.76,106.3
  rectangle: -190.94,78.74 -183.07,106.3
  rectangle: -171.26,78.74 -163.39,106.3
  rectangle: -151.57,78.74 -143.7,106.3
  rectangle: -131.89,78.74 -124.02,106.3
  rectangle: -112.2,78.74 -104.33,106.3
  rectangle: -92.52,78.74 -84.65,106.3
  rectangle: -72.83,78.74 -64.96,106.3
  rectangle: -53.15,78.74 -45.28,106.3
  rectangle: -33.46,78.74 -25.59,106.3
  rectangle: -13.78,78.74 -5.91,106.3
  rectangle: 5.91,78.74 13.78,106.3
  rectangle: 25.59,78.74 33.46,106.3
  rectangle: 45.28,78.74 53.15,106.3
  rectangle: 64.96,78.74 72.83,106.3
  rectangle: 84.65,78.74 92.52,106.3
  rectangle: 104.33,78.74 112.2,106.3
  rectangle: 124.02,78.74 131.89,106.3
  rectangle: 143.7,78.74 151.57,106.3
  rectangle: 163.39,78.74 171.26,106.3
  rectangle: 183.07,78.74 190.94,106.3
  rectangle: 202.76,78.74 210.63,106.3
  lines w4: -303.15,74.8 -303.15,27.56 -332.68,27.56 -332.68,35.43 -311.02,35.43 -309.06,37.4 -309.06,57.09 -332.68,57.09 -332.68,64.96 -309.06,64.96 -309.06,76.77 -303.15,76.77 ; 303.15,74.8 303.15,27.56 332.68,27.56 332.68,35.43 311.02,35.43 309.06,37.4 309.06,57.09 332.68,57.09 332.68,64.96 309.06,64.96 309.06,76.77 303.15,76.77
  lines w8: -297.24,-55.12 -297.24,74.8 297.24,74.8 297.24,-55.12

## 52745-2390 [mil]
pads (23):
  rect 11.81x31.5 smd: 1(-216.54,98.43) 2(-196.85,98.43) 3(-177.17,98.43) 4(-157.48,98.43) 5(-137.8,98.43) 6(-118.11,98.43) 7(-98.43,98.43) 8(-78.74,98.43) 9(-59.06,98.43) 10(-39.37,98.43) 11(-19.69,98.43) 12(0,98.43) 13(19.69,98.43) 14(39.37,98.43) 15(59.06,98.43) 16(78.74,98.43) 17(98.43,98.43) 18(118.11,98.43) 19(137.8,98.43) 20(157.48,98.43) 21(177.17,98.43) 22(196.85,98.43) 23(216.54,98.43)
Top Layer:
  rectangle: -360.24,-7.87 -265.75,78.74
  rectangle: -316.93,-41.34 -265.75,-7.87
  rectangle: 265.75,-41.34 316.93,-7.87
  rectangle: 265.75,-7.87 360.24,78.74
Top Overlay:
  region: 0,0 10,0 10,10 0,10
  lines w4: -228.35,-122.05 -228.35,-137.8 -218.5,-127.95 -218.5,-122.05 ; 218.5,-122.05 218.5,-127.95 228.35,-137.8 228.35,-122.05
  lines w8: -307.09,-55.12 307.09,-55.12 ; -285.43,-114.17 -285.43,-59.06 ; -251.97,-49.21 -251.97,39.37 cw(c-249.01,39.37) -246.06,39.37 -246.06,-49.21 ; 246.06,-49.21 246.06,39.37 cw(c249.01,39.37) 251.97,39.37 251.97,-49.21 ; 285.43,-114.17 285.43,-59.06 ; -342.52,-137.8 -342.52,-118.11 342.52,-118.11 342.52,-137.8 338.58,-141.73 -338.58,-141.73 -342.52,-137.8
Top Paste:
  region: 352.36,72.83 273.62,72.83 273.62,-1.97 352.36,-1.97
  rectangle: -352.36,-1.97 -273.62,72.83
Top Solder:
  region: 360.24,78.74 314.96,78.74 314.96,-7.87 360.24,-7.87
  region: 316.93,78.74 265.75,78.74 265.75,-41.34 316.93,-41.34
  rectangle: -360.24,-7.87 -314.96,78.74
  rectangle: -316.93,-41.34 -265.75,78.74
Mechanical 16:
  rectangle: -220.47,78.74 -212.6,106.3
  rectangle: -200.79,78.74 -192.91,106.3
  rectangle: -181.1,78.74 -173.23,106.3
  rectangle: -161.42,78.74 -153.54,106.3
  rectangle: -141.73,78.74 -133.86,106.3
  rectangle: -122.05,78.74 -114.17,106.3
  rectangle: -102.36,78.74 -94.49,106.3
  rectangle: -82.68,78.74 -74.8,106.3
  rectangle: -62.99,78.74 -55.12,106.3
  rectangle: -43.31,78.74 -35.43,106.3
  rectangle: -23.62,78.74 -15.75,106.3
  rectangle: -3.94,78.74 3.94,106.3
  rectangle: 15.75,78.74 23.62,106.3
  rectangle: 35.43,78.74 43.31,106.3
  rectangle: 55.12,78.74 62.99,106.3
  rectangle: 74.8,78.74 82.68,106.3
  rectangle: 94.49,78.74 102.36,106.3
  rectangle: 114.17,78.74 122.05,106.3
  rectangle: 133.86,78.74 141.73,106.3
  rectangle: 153.54,78.74 161.42,106.3
  rectangle: 173.23,78.74 181.1,106.3
  rectangle: 192.91,78.74 200.79,106.3
  rectangle: 212.6,78.74 220.47,106.3
  lines w4: -312.99,74.8 -312.99,27.56 -342.52,27.56 -342.52,35.43 -320.87,35.43 -318.9,37.4 -318.9,57.09 -342.52,57.09 -342.52,64.96 -318.9,64.96 -318.9,76.77 -312.99,76.77 ; 312.99,74.8 312.99,27.56 342.52,27.56 342.52,35.43 320.87,35.43 318.9,37.4 318.9,57.09 342.52,57.09 342.52,64.96 318.9,64.96 318.9,76.77 312.99,76.77
  lines w8: -307.09,-55.12 -307.09,74.8 307.09,74.8 307.09,-55.12

## 52745-2490 [mil]
pads (24):
  rect 11.81x31.5 smd: 1(-226.38,98.43) 2(-206.69,98.43) 3(-187.01,98.43) 4(-167.32,98.43) 5(-147.64,98.43) 6(-127.95,98.43) 7(-108.27,98.43) 8(-88.58,98.43) 9(-68.9,98.43) 10(-49.21,98.43) 11(-29.53,98.43) 12(-9.84,98.43) 13(9.84,98.43) 14(29.53,98.43) 15(49.21,98.43) 16(68.9,98.43) 17(88.58,98.43) 18(108.27,98.43) 19(127.95,98.43) 20(147.64,98.43) 21(167.32,98.43) 22(187.01,98.43) 23(206.69,98.43) 24(226.38,98.43)
Top Layer:
  rectangle: -370.08,-7.87 -275.59,78.74
  rectangle: -326.77,-41.34 -275.59,-7.87
  rectangle: 275.59,-41.34 326.77,-7.87
  rectangle: 275.59,-7.87 370.08,78.74
Top Overlay:
  region: 0,0 10,0 10,10 0,10
  lines w4: -238.19,-122.05 -238.19,-137.8 -228.35,-127.95 -228.35,-122.05 ; 228.35,-122.05 228.35,-127.95 238.19,-137.8 238.19,-122.05
  lines w8: -316.93,-55.12 316.93,-55.12 ; -295.28,-114.17 -295.28,-59.06 ; -261.81,-49.21 -261.81,39.37 cw(c-258.86,39.37) -255.91,39.37 -255.91,-49.21 ; 255.91,-49.21 255.91,39.37 cw(c258.86,39.37) 261.81,39.37 261.81,-49.21 ; 295.28,-114.17 295.28,-59.06 ; -352.36,-137.8 -352.36,-118.11 352.36,-118.11 352.36,-137.8 348.43,-141.73 -348.43,-141.73 -352.36,-137.8
Top Paste:
  region: 362.2,72.83 283.46,72.83 283.46,-1.97 362.2,-1.97
  rectangle: -362.2,-1.97 -283.46,72.83
Top Solder:
  region: 370.08,78.74 324.8,78.74 324.8,-7.87 370.08,-7.87
  region: 326.77,78.74 275.59,78.74 275.59,-41.34 326.77,-41.34
  rectangle: -370.08,-7.87 -324.8,78.74
  rectangle: -326.77,-41.34 -275.59,78.74
Mechanical 16:
  rectangle: -230.32,78.74 -222.44,106.3
  rectangle: -210.63,78.74 -202.76,106.3
  rectangle: -190.94,78.74 -183.07,106.3
  rectangle: -171.26,78.74 -163.39,106.3
  rectangle: -151.57,78.74 -143.7,106.3
  rectangle: -131.89,78.74 -124.02,106.3
  rectangle: -112.2,78.74 -104.33,106.3
  rectangle: -92.52,78.74 -84.65,106.3
  rectangle: -72.83,78.74 -64.96,106.3
  rectangle: -53.15,78.74 -45.28,106.3
  rectangle: -33.46,78.74 -25.59,106.3
  rectangle: -13.78,78.74 -5.91,106.3
  rectangle: 5.91,78.74 13.78,106.3
  rectangle: 25.59,78.74 33.46,106.3
  rectangle: 45.28,78.74 53.15,106.3
  rectangle: 64.96,78.74 72.83,106.3
  rectangle: 84.65,78.74 92.52,106.3
  rectangle: 104.33,78.74 112.2,106.3
  rectangle: 124.02,78.74 131.89,106.3
  rectangle: 143.7,78.74 151.57,106.3
  rectangle: 163.39,78.74 171.26,106.3
  rectangle: 183.07,78.74 190.94,106.3
  rectangle: 202.76,78.74 210.63,106.3
  rectangle: 222.44,78.74 230.32,106.3
  lines w4: -322.83,74.8 -322.83,27.56 -352.36,27.56 -352.36,35.43 -330.71,35.43 -328.74,37.4 -328.74,57.09 -352.36,57.09 -352.36,64.96 -328.74,64.96 -328.74,76.77 -322.83,76.77 ; 322.83,74.8 322.83,27.56 352.36,27.56 352.36,35.43 330.71,35.43 328.74,37.4 328.74,57.09 352.36,57.09 352.36,64.96 328.74,64.96 328.74,76.77 322.83,76.77
  lines w8: -316.93,-55.12 -316.93,74.8 316.93,74.8 316.93,-55.12

## 52745-2590 [mil]
pads (25):
  rect 11.81x31.5 smd: 1(-236.22,98.43) 2(-216.54,98.43) 3(-196.85,98.43) 4(-177.17,98.43) 5(-157.48,98.43) 6(-137.8,98.43) 7(-118.11,98.43) 8(-98.43,98.43) 9(-78.74,98.43) 10(-59.06,98.43) 11(-39.37,98.43) 12(-19.69,98.43) 13(0,98.43) 14(19.69,98.43) 15(39.37,98.43) 16(59.06,98.43) 17(78.74,98.43) 18(98.43,98.43) 19(118.11,98.43) 20(137.8,98.43) 21(157.48,98.43) 22(177.17,98.43) 23(196.85,98.43) 24(216.54,98.43) 25(236.22,98.43)
Top Layer:
  rectangle: -379.92,-7.87 -285.43,78.74
  rectangle: -336.61,-41.34 -285.43,-7.87
  rectangle: 285.43,-41.34 336.61,-7.87
  rectangle: 285.43,-7.87 379.92,78.74
Top Overlay:
  region: 0,0 10,0 10,10 0,10
  lines w4: -248.03,-122.05 -248.03,-137.8 -238.19,-127.95 -238.19,-122.05 ; 238.19,-122.05 238.19,-127.95 248.03,-137.8 248.03,-122.05
  lines w8: -326.77,-55.12 326.77,-55.12 ; -305.12,-114.17 -305.12,-59.06 ; -271.65,-49.21 -271.65,39.37 cw(c-268.7,39.37) -265.75,39.37 -265.75,-49.21 ; 265.75,-49.21 265.75,39.37 cw(c268.7,39.37) 271.65,39.37 271.65,-49.21 ; 305.12,-114.17 305.12,-59.06 ; -362.2,-137.8 -362.2,-118.11 362.2,-118.11 362.2,-137.8 358.27,-141.73 -358.27,-141.73 -362.2,-137.8
Top Paste:
  region: 372.05,72.83 293.31,72.83 293.31,-1.97 372.05,-1.97
  rectangle: -372.05,-1.97 -293.31,72.83
Top Solder:
  region: 379.92,78.74 334.65,78.74 334.65,-7.87 379.92,-7.87
  region: 336.61,78.74 285.43,78.74 285.43,-41.34 336.61,-41.34
  rectangle: -379.92,-7.87 -334.65,78.74
  rectangle: -336.61,-41.34 -285.43,78.74
Mechanical 16:
  rectangle: -240.16,78.74 -232.28,106.3
  rectangle: -220.47,78.74 -212.6,106.3
  rectangle: -200.79,78.74 -192.91,106.3
  rectangle: -181.1,78.74 -173.23,106.3
  rectangle: -161.42,78.74 -153.54,106.3
  rectangle: -141.73,78.74 -133.86,106.3
  rectangle: -122.05,78.74 -114.17,106.3
  rectangle: -102.36,78.74 -94.49,106.3
  rectangle: -82.68,78.74 -74.8,106.3
  rectangle: -62.99,78.74 -55.12,106.3
  rectangle: -43.31,78.74 -35.43,106.3
  rectangle: -23.62,78.74 -15.75,106.3
  rectangle: -3.94,78.74 3.94,106.3
  rectangle: 15.75,78.74 23.62,106.3
  rectangle: 35.43,78.74 43.31,106.3
  rectangle: 55.12,78.74 62.99,106.3
  rectangle: 74.8,78.74 82.68,106.3
  rectangle: 94.49,78.74 102.36,106.3
  rectangle: 114.17,78.74 122.05,106.3
  rectangle: 133.86,78.74 141.73,106.3
  rectangle: 153.54,78.74 161.42,106.3
  rectangle: 173.23,78.74 181.1,106.3
  rectangle: 192.91,78.74 200.79,106.3
  rectangle: 212.6,78.74 220.47,106.3
  rectangle: 232.28,78.74 240.16,106.3
  lines w4: -332.68,74.8 -332.68,27.56 -362.2,27.56 -362.2,35.43 -340.55,35.43 -338.58,37.4 -338.58,57.09 -362.2,57.09 -362.2,64.96 -338.58,64.96 -338.58,76.77 -332.68,76.77 ; 332.68,74.8 332.68,27.56 362.2,27.56 362.2,35.43 340.55,35.43 338.58,37.4 338.58,57.09 362.2,57.09 362.2,64.96 338.58,64.96 338.58,76.77 332.68,76.77
  lines w8: -326.77,-55.12 -326.77,74.8 326.77,74.8 326.77,-55.12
